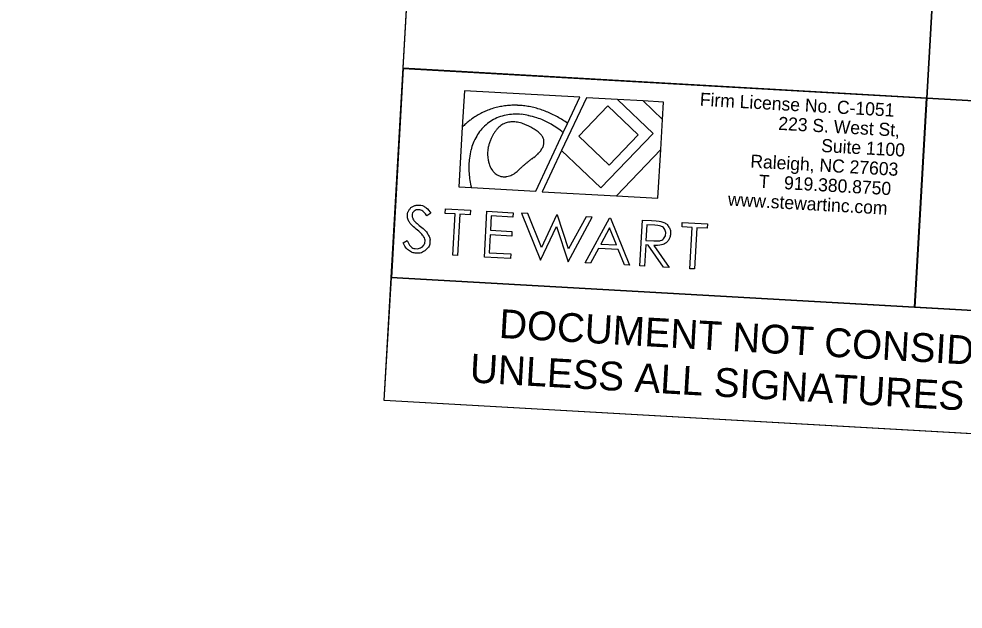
# Model space of a CAD drawing. Extents: x 2602909 to 2604669, y 617940 to 619640.
# Drawn here: x 2604361.6 to 2604541.7, y 618785.4 to 618898.1 of the extents above; entities that cross this region are included whole.
import ezdxf

# ---------------------------------------------------------------- set-up
doc = ezdxf.new("R2010")
doc.units = 0
for name, color, linetype in [('Default', 7, 'Continuous'), ('Scratch_Level_1', 7, 'Continuous'), ('Sheet Plan And Profile CELL', 7, 'Continuous')]:
    doc.layers.add(name, color=color, linetype=linetype)

msp = doc.modelspace()

# ---------------------------------------------------------------- linework, layer by layer
at = {"layer": 'Default'}
for p, q in [((2604541.21, 618995.27), (2604534.83, 618882.99)), ((2604446.6, 618884.37), (2604446.21, 618877.42)), ((2604468.64, 618883.11), (2604446.6, 618884.37)), ((2604469.87, 618883.04), (2604465.14, 618872.98)), ((2604466.3, 618878.13), (2604468.64, 618883.11)), ((2604475.81, 618882.7), (2604469.87, 618883.04)), ((2604475.81, 618882.7), (2604482.61, 618876.21)), ((2604480.7, 618882.42), (2604475.81, 618882.7)), ((2604482.61, 618876.21), (2604475.81, 618882.7)), ((2604452.44, 618881.09), (2604452.39, 618881.08)), ((2604458.97, 618881.33), (2604458.98, 618881.33)), ((2604484.58, 618882.2), (2604480.7, 618882.42)), ((2604480.7, 618882.42), (2604484.39, 618878.9)), ((2604484.39, 618878.9), (2604480.7, 618882.42)), ((2604484.39, 618878.9), (2604484.58, 618882.2)), ((2604451.35, 618880.75), (2604451.32, 618880.72)), ((2604458.79, 618879.63), (2604458.83, 618879.65)), ((2604464.35, 618879.36), (2604464.36, 618879.36)), ((2604446.21, 618877.42), (2604445.56, 618865.99)), ((2604465.47, 618876.36), (2604466.3, 618878.13)), ((2604484.06, 618873.14), (2604484.39, 618878.9)), ((2604460.21, 618865.16), (2604465.47, 618876.36)), ((2604482.61, 618876.21), (2604472.66, 618865.8)), ((2604472.66, 618865.8), (2604482.61, 618876.21)), ((2604474.23, 618870.18), (2604479.75, 618875.96)), ((2604465.14, 618872.98), (2604461.44, 618865.09)), ((2604472.66, 618865.8), (2604465.14, 618872.98)), ((2604465.14, 618872.98), (2604472.66, 618865.8)), ((2604484.06, 618873.14), (2604475.6, 618864.28)), ((2604475.6, 618864.28), (2604484.06, 618873.14)), ((2604483.53, 618863.83), (2604484.06, 618873.14)), ((2604445.56, 618865.99), (2604447.93, 618865.86)), ((2604447.93, 618865.86), (2604460.21, 618865.16)), ((2604461.44, 618865.09), (2604475.6, 618864.28)), ((2604475.6, 618864.28), (2604483.53, 618863.83)), ((2604458.7, 618860.91), (2604457.51, 618860.97)), ((2604457.51, 618860.97), (2604461.13, 618852)), ((2604461.32, 618854.44), (2604458.7, 618860.91)), ((2604464.19, 618860.59), (2604461.32, 618854.44)), ((2604464.36, 618860.58), (2604464.19, 618860.59)), ((2604466.48, 618854.15), (2604464.36, 618860.58)), ((2604466.38, 618851.71), (2604471, 618860.21)), ((2604469.81, 618860.27), (2604466.48, 618854.15)), ((2604471, 618860.21), (2604469.81, 618860.27)), ((2604461.13, 618852), (2604464.16, 618858.47)), ((2604464.16, 618858.47), (2604466.38, 618851.71)), ((2604431.33, 618825.24), (2604432.67, 618848.7)), ((2604431.33, 618825.24), (2604432.67, 618848.7)), ((2604432.67, 618848.7), (2604632.38, 618837.33)), ((2604432.67, 618848.7), (2604632.38, 618837.33)), ((2604631.04, 618813.87), (2604431.33, 618825.24)), ((2604631.04, 618813.87), (2604431.33, 618825.24))]:
    msp.add_line(p, q, dxfattribs=at)
for points in [[(2604434.93, 618888.64), (2604534.77, 618882.95), (2604532.49, 618843.02), (2604432.65, 618848.7)], [(2604534.77, 618882.95), (2604434.93, 618888.64), (2604432.65, 618848.7), (2604532.49, 618843.02)], [(2604534.82, 618882.95), (2604634.66, 618877.26), (2604632.38, 618837.33), (2604532.54, 618843.01)]]:
    msp.add_lwpolyline(points, close=True, dxfattribs=at)
for points in [[(2604468.43, 618875.72), (2604473.95, 618881.5), (2604479.75, 618875.96), (2604474.23, 618870.18), (2604468.43, 618875.72)], [(2604479.75, 618875.96), (2604473.95, 618881.5), (2604468.43, 618875.72), (2604474.23, 618870.18)], [(2604450.37, 618880.33), (2604450.45, 618880.37)], [(2604460.44, 618879.2), (2604460.39, 618879.19)], [(2604446.95, 618878.11), (2604446.89, 618878.07)], [(2604459.56, 618871.43), (2604459.44, 618871.34)], [(2604459.75, 618871.56), (2604459.67, 618871.51)], [(2604459.89, 618871.63), (2604459.81, 618871.6)], [(2604457.25, 618869.52), (2604457.14, 618869.42)], [(2604442.92, 618860.95), (2604442.97, 618861.8), (2604447.75, 618861.53), (2604447.7, 618860.67), (2604445.76, 618860.79), (2604445.31, 618852.91), (2604444.42, 618852.96), (2604444.87, 618860.84), (2604442.92, 618860.95)], [(2604450.91, 618861.35), (2604455.92, 618861.07), (2604455.87, 618860.21), (2604451.74, 618860.45), (2604451.58, 618857.71), (2604455.68, 618857.47), (2604455.63, 618856.62), (2604451.53, 618856.85), (2604451.34, 618853.42), (2604455.44, 618853.19), (2604455.39, 618852.33), (2604450.42, 618852.61), (2604450.91, 618861.35)], [(2604440.2, 618860.96), (2604439.45, 618860.46)], [(2604474.5, 618860.01), (2604478.07, 618851.04), (2604477.13, 618851.09), (2604475.92, 618854.05), (2604472.16, 618854.26), (2604470.64, 618851.46), (2604469.66, 618851.52), (2604474.29, 618860.02), (2604474.5, 618860.01)], [(2604482.76, 618854.84), (2604485.67, 618850.61), (2604484.59, 618850.67), (2604481.68, 618854.9), (2604481.19, 618854.93), (2604480.96, 618850.88), (2604480.09, 618850.93), (2604480.58, 618859.66)], [(2604480.58, 618859.66), (2604482.32, 618859.56)], [(2604474.28, 618858.16), (2604472.61, 618855.08), (2604475.59, 618854.91), (2604474.28, 618858.16)], [(2604481.4, 618858.76), (2604481.24, 618855.78), (2604482.74, 618855.69)], [(2604482.94, 618858.67), (2604481.4, 618858.76)], [(2604488.12, 618858.37), (2604488.17, 618859.23), (2604492.95, 618858.96), (2604492.9, 618858.1), (2604490.95, 618858.21), (2604490.51, 618850.33), (2604489.61, 618850.38), (2604490.06, 618858.26), (2604488.12, 618858.37)], [(2604434.9, 618855.35), (2604435.67, 618855.75)]]:
    msp.add_lwpolyline(points, dxfattribs=at)
for centre, radius, start, end in [((2604456.15, 618867.48), 14.11, 105.4351, 109.8733), ((2604456.15, 618867.48), 14.11, 105.4351, 109.8733), ((2604456.04, 618868.05), 13.53, 100.9183, 105.4351), ((2604456.04, 618868.05), 13.53, 100.9183, 105.4351), ((2604456.15, 618867.48), 14.11, 96.4841, 100.9183), ((2604456.15, 618867.48), 14.11, 96.4841, 100.9183), ((2604456.17, 618867.29), 14.3, 92.0792, 96.4841), ((2604456.17, 618867.29), 14.3, 92.0792, 96.4841), ((2604456.18, 618867.02), 14.57, 87.7544, 92.0792), ((2604456.18, 618867.02), 14.57, 87.7544, 92.0792), ((2604456.15, 618866.14), 15.45, 83.5548, 87.7544), ((2604456.15, 618866.14), 15.45, 83.5548, 87.7544), ((2604456.15, 618866.14), 15.45, 79.4225, 83.5548), ((2604456.15, 618866.14), 15.45, 79.4225, 83.5548), ((2604455.87, 618864.69), 16.93, 75.4903, 79.4225), ((2604455.87, 618864.69), 16.93, 75.4903, 79.4225), ((2604456.01, 618865.25), 16.35, 71.6037, 75.4903), ((2604456.01, 618865.25), 16.35, 71.6037, 75.4903), ((2604456.76, 618866.9), 14.9, 123.1234, 127.2527), ((2604456.76, 618866.9), 14.9, 123.1234, 127.2527), ((2604455.78, 618868.39), 13.11, 118.7212, 123.1234), ((2604455.78, 618868.39), 13.11, 118.7212, 123.1234), ((2604456.34, 618867.37), 14.27, 114.3893, 118.7212), ((2604456.34, 618867.37), 14.27, 114.3893, 118.7212), ((2604455.78, 618868.39), 13.11, 109.8733, 114.3893), ((2604455.78, 618868.39), 13.11, 109.8733, 114.3893), ((2604456.01, 618871.77), 8.06, 110.9978, 120.9124), ((2604456.01, 618871.77), 8.06, 110.9978, 120.9124), ((2604456.43, 618870.68), 9.23, 101.7301, 110.9978), ((2604456.43, 618870.68), 9.23, 101.7301, 110.9978), ((2604456.31, 618871.24), 8.65, 92.7105, 101.7301), ((2604456.31, 618871.24), 8.65, 92.7105, 101.7301), ((2604456.47, 618867.94), 11.96, 85.0393, 92.7105), ((2604456.47, 618867.94), 11.96, 85.0393, 92.7105), ((2604456.62, 618869.69), 10.21, 77.5039, 85.0393), ((2604456.62, 618869.69), 10.21, 77.5039, 85.0393), ((2604455.37, 618864.22), 15.79, 71.4506, 77.5039), ((2604455.37, 618864.22), 15.79, 71.4506, 77.5039), ((2604456.56, 618867.64), 12.19, 65.3226, 71.4506), ((2604456.56, 618867.64), 12.19, 65.3226, 71.4506), ((2604455.27, 618863.04), 18.68, 67.9682, 71.6037), ((2604455.27, 618863.04), 18.68, 67.9682, 71.6037), ((2604455.71, 618864.11), 17.52, 64.3511, 67.9682), ((2604455.71, 618864.11), 17.52, 64.3511, 67.9682), ((2604454.38, 618861.34), 20.6, 61.0149, 64.3511), ((2604454.38, 618861.34), 20.6, 61.0149, 64.3511), ((2604454.78, 618862.07), 19.77, 57.6686, 61.0149), ((2604454.78, 618862.07), 19.77, 57.6686, 61.0149), ((2604456.34, 618867.37), 14.27, 131.4472, 135.2253), ((2604456.34, 618867.37), 14.27, 131.4472, 135.2253), ((2604456.14, 618867.7), 13.88, 127.2527, 131.4472), ((2604456.14, 618867.7), 13.88, 127.2527, 131.4472), ((2604456.52, 618871.2), 8.82, 130.9224, 140.4448), ((2604456.52, 618871.2), 8.82, 130.9224, 140.4448), ((2604455.97, 618871.83), 7.98, 120.9124, 130.9224), ((2604455.97, 618871.83), 7.98, 120.9124, 130.9224), ((2604456.14, 618874.18), 4.37, 129.5899, 135.8946), ((2604456.14, 618874.18), 4.37, 129.5899, 135.8946), ((2604455.96, 618874.39), 4.1, 122.8405, 129.5899), ((2604455.96, 618874.39), 4.1, 122.8405, 129.5899), ((2604455.77, 618874.7), 3.73, 115.7662, 122.8405), ((2604455.77, 618874.7), 3.73, 115.7662, 122.8405), ((2604455.74, 618874.76), 3.66, 108.568, 115.7662), ((2604455.74, 618874.76), 3.66, 108.568, 115.7662), ((2604455.77, 618874.66), 3.77, 101.4688, 108.568), ((2604455.77, 618874.66), 3.77, 101.4688, 108.568), ((2604455.8, 618874.53), 3.9, 94.642, 101.4688), ((2604455.8, 618874.53), 3.9, 94.642, 101.4688), ((2604455.84, 618873.94), 4.49, 88.28, 94.642), ((2604455.84, 618873.94), 4.49, 88.28, 94.642), ((2604455.83, 618873.59), 4.84, 82.4228, 88.28), ((2604455.83, 618873.59), 4.84, 82.4228, 88.28), ((2604455.68, 618872.43), 6.01, 77.1673, 82.4228), ((2604455.68, 618872.43), 6.01, 77.1673, 82.4228), ((2604455.55, 618871.87), 6.59, 72.4373, 77.1673), ((2604455.55, 618871.87), 6.59, 72.4373, 77.1673), ((2604454.98, 618870.06), 8.48, 68.2695, 72.4373), ((2604454.98, 618870.06), 8.48, 68.2695, 72.4373), ((2604454.23, 618868.17), 10.52, 64.5402, 68.2694), ((2604454.23, 618868.17), 10.52, 64.5402, 68.2694), ((2604455.13, 618870.07), 8.42, 60.3723, 64.5402), ((2604455.13, 618870.07), 8.42, 60.3723, 64.5402), ((2604456.45, 618871.43), 6.6, 60.6425, 64.5301), ((2604456.45, 618871.43), 6.6, 60.6425, 64.5301), ((2604453.3, 618860.56), 19.99, 60.538, 65.3226), ((2604453.3, 618860.56), 19.99, 60.538, 65.3226), ((2604455.37, 618864.22), 15.79, 55.5186, 60.538), ((2604455.37, 618864.22), 15.79, 55.5186, 60.538), ((2604454.78, 618862.07), 19.77, 54.3325, 57.6686), ((2604454.78, 618862.07), 19.77, 54.3325, 57.6686), ((2604458.52, 618870.16), 11.07, 149.8427, 157.9091), ((2604458.52, 618870.16), 11.07, 149.8427, 157.9091), ((2604456.01, 618871.62), 8.16, 140.4448, 149.8427), ((2604456.01, 618871.62), 8.16, 140.4448, 149.8427), ((2604459.15, 618872.03), 8.09, 151.4424, 155.566), ((2604459.15, 618872.03), 8.09, 151.4424, 155.566), ((2604458.48, 618872.39), 7.33, 146.8316, 151.4424), ((2604458.48, 618872.39), 7.33, 146.8316, 151.4424), ((2604457.18, 618873.24), 5.77, 141.6353, 146.8316), ((2604457.18, 618873.24), 5.77, 141.6353, 146.8316), ((2604456.78, 618873.55), 5.27, 135.8946, 141.6353), ((2604456.78, 618873.55), 5.27, 135.8946, 141.6353), ((2604455.44, 618869.63), 8.66, 57.2494, 60.6425), ((2604455.44, 618869.63), 8.66, 57.2494, 60.6425), ((2604456.52, 618871.31), 6.66, 53.3617, 57.2494), ((2604456.52, 618871.31), 6.66, 53.3617, 57.2494), ((2604457.59, 618872.75), 4.87, 48.816, 53.3617), ((2604457.59, 618872.75), 4.87, 48.816, 53.3617), ((2604457.97, 618873.18), 4.29, 43.5847, 48.816), ((2604457.97, 618873.18), 4.29, 43.5847, 48.816), ((2604458.77, 618873.94), 3.19, 37.517, 43.5847), ((2604458.77, 618873.94), 3.19, 37.517, 43.5847), ((2604459.05, 618874.16), 2.84, 30.6364, 37.517), ((2604459.05, 618874.16), 2.84, 30.6364, 37.517), ((2604459.55, 618874.45), 2.26, 22.9285, 30.6364), ((2604459.55, 618874.45), 2.26, 22.9285, 30.6364), ((2604454.47, 618862.91), 17.37, 50.734, 55.5186), ((2604454.47, 618862.91), 17.37, 50.734, 55.5186), ((2604456.99, 618870.79), 9.4, 157.9091, 165.8682), ((2604456.99, 618870.79), 9.4, 157.9091, 165.8682), ((2604461.18, 618870.94), 10.38, 162.434, 166.0583), ((2604461.18, 618870.94), 10.38, 162.434, 166.0583), ((2604463.64, 618870.16), 12.95, 159.1904, 162.434), ((2604463.64, 618870.16), 12.95, 159.1904, 162.434), ((2604461.31, 618871.04), 10.47, 155.566, 159.1904), ((2604461.31, 618871.04), 10.47, 155.566, 159.1904), ((2604458.92, 618874.79), 2.9, 334.5948, 341.3707), ((2604458.92, 618874.79), 2.9, 334.5948, 341.3707), ((2604459.7, 618874.52), 2.1, 14.5996, 22.9285), ((2604459.7, 618874.52), 2.1, 14.5996, 22.9285), ((2604459.49, 618874.6), 2.3, 341.3707, 348.9846), ((2604459.49, 618874.6), 2.3, 341.3707, 348.9846), ((2604459.86, 618874.56), 1.93, 5.9113, 14.5996), ((2604459.86, 618874.56), 1.93, 5.9113, 14.5996), ((2604459.66, 618874.57), 2.13, 348.9846, 357.2472), ((2604459.66, 618874.57), 2.13, 348.9846, 357.2472), ((2604459.86, 618874.56), 1.93, 357.2472, 5.9113), ((2604459.86, 618874.56), 1.93, 357.2472, 5.9113), ((2604461.97, 618869.53), 14.55, 165.8682, 172.2658), ((2604461.97, 618869.53), 14.55, 165.8682, 172.2658), ((2604457.81, 618872.4), 6.78, 175.8527, 180.2474), ((2604457.81, 618872.4), 6.78, 175.8527, 180.2474), ((2604459.78, 618872.41), 8.75, 180.2474, 184.4016), ((2604459.78, 618872.41), 8.75, 180.2474, 184.4016), ((2604458.62, 618872.34), 7.59, 171.6986, 175.8527), ((2604458.62, 618872.34), 7.59, 171.6986, 175.8527), ((2604455.7, 618876.97), 6.78, 308.0645, 311.8816), ((2604455.7, 618876.97), 6.78, 308.0645, 311.8816), ((2604454.29, 618878.55), 8.89, 311.8816, 315.2147), ((2604454.29, 618878.55), 8.89, 311.8816, 315.2147), ((2604455.75, 618877.11), 6.85, 315.2147, 319.0318), ((2604455.75, 618877.11), 6.85, 315.2147, 319.0318), ((2604457.13, 618875.9), 5.01, 319.0318, 323.4941), ((2604457.13, 618875.9), 5.01, 319.0318, 323.4941), ((2604457.61, 618875.54), 4.41, 323.4941, 328.6309), ((2604457.61, 618875.54), 4.41, 323.4941, 328.6309), ((2604458.59, 618874.95), 3.27, 328.6309, 334.5948), ((2604458.59, 618874.95), 3.27, 328.6309, 334.5948), ((2604466.05, 618869.81), 18.6, 178.7275, 183.7519), ((2604466.05, 618869.81), 18.6, 178.7275, 183.7519), ((2604458.7, 618869.98), 11.25, 172.2658, 178.7275), ((2604458.7, 618869.98), 11.25, 172.2658, 178.7275), ((2604456.43, 618872.15), 5.39, 184.4016, 189.6957), ((2604456.43, 618872.15), 5.39, 184.4016, 189.6957), ((2604458.01, 618872.42), 6.99, 189.6957, 194.9243), ((2604458.01, 618872.42), 6.99, 189.6957, 194.9243), ((2604455.56, 618871.77), 4.45, 194.9243, 201.4764), ((2604455.56, 618871.77), 4.45, 194.9243, 201.4764), ((2604456.2, 618872.02), 5.14, 201.4764, 208.2505), ((2604456.2, 618872.02), 5.14, 201.4764, 208.2505), ((2604481.2, 618842.97), 35.75, 130.6166, 130.989), ((2604481.2, 618842.97), 35.75, 130.6166, 130.989), ((2604488.41, 618834.55), 46.84, 130.277, 130.6166), ((2604488.41, 618834.55), 46.84, 130.277, 130.6166), ((2604483.57, 618840.27), 39.35, 129.9065, 130.277), ((2604483.57, 618840.27), 39.35, 129.9065, 130.277), ((2604486.17, 618837.16), 43.39, 129.5378, 129.9065), ((2604486.17, 618837.16), 43.39, 129.5378, 129.9065), ((2604481.64, 618842.65), 36.29, 129.1346, 129.5378), ((2604481.64, 618842.65), 36.29, 129.1346, 129.5378), ((2604479.6, 618845.16), 33.05, 128.6918, 129.1346), ((2604479.6, 618845.16), 33.05, 128.6918, 129.1346), ((2604475.92, 618849.75), 27.17, 128.2035, 128.6918), ((2604475.92, 618849.75), 27.17, 128.2035, 128.6918), ((2604471.62, 618855.22), 20.21, 127.6053, 128.2035), ((2604471.62, 618855.22), 20.21, 127.6053, 128.2035), ((2604468.93, 618858.7), 15.81, 126.929, 127.6053), ((2604468.93, 618858.7), 15.81, 126.929, 127.6053), ((2604465.16, 618863.72), 9.52, 125.9896, 126.929), ((2604463.45, 618866.08), 6.61, 124.8621, 125.9896), ((2604463.45, 618866.08), 6.61, 124.8621, 125.9896), ((2604461.46, 618868.93), 3.14, 123.0144, 124.8621), ((2604460.65, 618870.19), 1.64, 120.4582, 123.0144), ((2604460.65, 618870.19), 1.64, 120.4582, 123.0144), ((2604459.94, 618871.39), 0.249, 114.801, 120.4583), ((2604460.35, 618870.5), 1.22, 112.2448, 114.8011), ((2604462.32, 618869.57), 14.86, 183.7519, 188.9947), ((2604462.32, 618869.57), 14.86, 183.7519, 188.9947), ((2604454.78, 618871.26), 3.53, 208.2505, 216.4264), ((2604454.78, 618871.26), 3.53, 208.2505, 216.4264), ((2604454.85, 618871.31), 3.62, 216.4264, 225.1491), ((2604454.85, 618871.31), 3.62, 216.4264, 225.1491), ((2604454.33, 618870.79), 2.88, 225.1491, 234.9243), ((2604454.33, 618870.79), 2.88, 225.1491, 234.9243), ((2604454.23, 618870.65), 2.71, 234.9243, 245.3087), ((2604454.23, 618870.65), 2.71, 234.9243, 245.3087), ((2604454.22, 618871.24), 3.28, 292.1193, 299.4606), ((2604454.22, 618871.24), 3.28, 292.1193, 299.4606), ((2604453.07, 618873.27), 5.62, 299.4606, 305.066), ((2604453.07, 618873.27), 5.62, 299.4606, 305.066), ((2604453.6, 618872.51), 4.68, 305.066, 310.7971), ((2604453.6, 618872.51), 4.68, 305.066, 310.7971), ((2604453.46, 618872.67), 4.9, 310.7971, 316.4024), ((2604453.46, 618872.67), 4.9, 310.7971, 316.4024), ((2604475.94, 618848.96), 27.78, 132.5821, 132.9564), ((2604475.94, 618848.96), 27.78, 132.5821, 132.9564), ((2604468.96, 618856.56), 17.46, 132.11, 132.5821), ((2604479.13, 618845.31), 32.63, 131.7357, 132.11), ((2604479.13, 618845.31), 32.63, 131.7357, 132.11), ((2604476, 618848.82), 27.93, 131.3312, 131.7357), ((2604476, 618848.82), 27.93, 131.3312, 131.7357), ((2604485.52, 618837.99), 42.35, 130.989, 131.3311), ((2604485.52, 618837.99), 42.35, 130.989, 131.3311), ((2604463.62, 618869.77), 16.17, 188.9947, 194.0191), ((2604463.62, 618869.77), 16.17, 188.9947, 194.0191), ((2604454.24, 618870.66), 2.73, 245.3087, 255.659), ((2604454.24, 618870.66), 2.73, 245.3087, 255.659), ((2604454.17, 618870.37), 2.43, 255.659, 266.2495), ((2604454.17, 618870.37), 2.43, 255.659, 266.2495), ((2604454.22, 618871.1), 3.16, 266.2495, 275.5332), ((2604454.22, 618871.1), 3.16, 266.2495, 275.5332), ((2604454.26, 618870.62), 2.67, 275.5332, 284.7506), ((2604454.26, 618870.62), 2.67, 275.5332, 284.7506), ((2604453.88, 618872.07), 4.18, 284.7505, 292.1193), ((2604453.88, 618872.07), 4.18, 284.7505, 292.1193)]:
    msp.add_arc(centre, radius, start, end, dxfattribs=at)
for points in [[(2604439.45, 618860.46), (2604439, 618861.14), (2604438.66, 618861.37), (2604438.33, 618861.6), (2604437.92, 618861.62), (2604437.39, 618861.65), (2604437.03, 618861.35), (2604436.68, 618861.05), (2604436.65, 618860.58), (2604436.64, 618860.3), (2604436.74, 618860.02), (2604436.84, 618859.75), (2604437.14, 618859.42), (2604437.3, 618859.24), (2604438.22, 618858.48), (2604439.31, 618857.58), (2604439.69, 618856.9), (2604440.07, 618856.22), (2604440.04, 618855.56), (2604439.98, 618854.61), (2604439.22, 618853.96), (2604438.46, 618853.3), (2604437.43, 618853.35), (2604436.63, 618853.4), (2604436.01, 618853.86), (2604435.39, 618854.32), (2604434.9, 618855.35)], [(2604435.67, 618855.75), (2604436.37, 618854.27), (2604437.4, 618854.21), (2604437.84, 618854.18), (2604438.23, 618854.37), (2604438.63, 618854.55), (2604438.85, 618854.88), (2604439.07, 618855.21), (2604439.09, 618855.6), (2604439.12, 618856.04), (2604438.85, 618856.48), (2604438.47, 618857.08), (2604437.43, 618857.96), (2604436.39, 618858.85), (2604436.14, 618859.23), (2604435.71, 618859.88), (2604435.75, 618860.6), (2604435.79, 618861.17), (2604436.09, 618861.62), (2604436.38, 618862.08), (2604436.9, 618862.32), (2604437.41, 618862.56), (2604437.99, 618862.53), (2604438.6, 618862.49), (2604439.12, 618862.15), (2604439.64, 618861.82), (2604440.2, 618860.96)], [(2604482.32, 618859.56), (2604483.77, 618859.48), (2604484.28, 618859.33), (2604485.05, 618859.11), (2604485.5, 618858.49), (2604485.95, 618857.88), (2604485.9, 618857.02), (2604485.86, 618856.31), (2604485.5, 618855.79), (2604485.13, 618855.27), (2604484.49, 618855.02), (2604483.86, 618854.78), (2604482.76, 618854.84)], [(2604482.74, 618855.69), (2604483.61, 618855.64), (2604484.04, 618855.78), (2604484.47, 618855.92), (2604484.72, 618856.27), (2604484.98, 618856.63), (2604485.01, 618857.08), (2604485.03, 618857.52), (2604484.81, 618857.89), (2604484.6, 618858.26), (2604484.22, 618858.44), (2604483.84, 618858.62), (2604482.94, 618858.67)]]:
    msp.add_open_spline(points, degree=3, dxfattribs=at)
at = {"layer": 'Scratch_Level_1'}
msp.add_lwpolyline([(2604574.88, 618817.07), (2604431.33, 618825.24), (2604442.75, 619025.97), (2603144.9, 619099.88), (2603085.2, 618051.58), (2604526.6, 617969.49)], close=True, dxfattribs=at)
msp.add_lwpolyline([(2604574.88, 618817.07), (2604431.33, 618825.24), (2604442.75, 619025.97), (2603144.9, 619099.88), (2603085.2, 618051.58), (2604526.6, 617969.49)], close=True, dxfattribs=at)
at = {"layer": 'Sheet Plan And Profile CELL'}
for p, q in [((2604434.93, 618888.64), (2604432.67, 618848.7)), ((2604534.82, 618882.95), (2604532.52, 618843.02)), ((2604432.67, 618848.7), (2604632.38, 618837.33))]:
    msp.add_line(p, q, dxfattribs=at)
for points in [[(2604441.33, 619000.96), (2604541.21, 618995.27), (2604534.82, 618882.94), (2604434.94, 618888.65)], [(2604541.21, 618995.27), (2604641.04, 618989.59), (2604634.66, 618877.26), (2604534.82, 618882.94)]]:
    msp.add_lwpolyline(points, close=True, dxfattribs=at)

# ---------------------------------------------------------------- texts
at = {"layer": 'Default'}
for s, height, p in [('Firm License No. C-1051', 2.5, (2604491.46, 618881.51)), ('223 S. West St,', 2.5, (2604506.43, 618876.91)), ('Suite 1100', 2.5, (2604514.61, 618872.68)), ('Raleigh, NC 27603', 2.5, (2604501.1, 618869.7)), ('T   919.380.8750', 2.5, (2604502.7, 618865.85)), ('www.stewartinc.com', 2.5, (2604496.83, 618862.43)), ('DOCUMENT NOT CONSIDERED FINAL', 5.5, (2604453.12, 618837.18)), ('DOCUMENT NOT CONSIDERED FINAL', 5.5, (2604453.12, 618837.18)), ('UNLESS ALL SIGNATURES COMPLETED', 5.5, (2604447.55, 618828.68)), ('UNLESS ALL SIGNATURES COMPLETED', 5.5, (2604447.55, 618828.68))]:
    msp.add_text(s, height=height, rotation=356.7403, dxfattribs=at).set_placement(p)

doc.saveas('drawing.dxf')
